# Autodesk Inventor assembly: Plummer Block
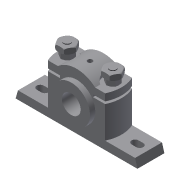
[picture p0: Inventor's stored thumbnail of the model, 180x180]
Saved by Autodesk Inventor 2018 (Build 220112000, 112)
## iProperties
Created: 2011-07
Part Number: Plummer Block
Document SubType Name: Assembly
Designer: CadCim
Author: CadCim
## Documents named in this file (7)
- E:\_Deepak\Inventor\Autodesk Inventor_2017_Project\Resources\Inventor_2018_tut\c09_Inv_tut_2018\c09_tut02_inv\Plummer Block\Plummer Block.iam
- E:\_Deepak\Inventor\Autodesk Inventor_2017_Project\Resources\Inventor_2018_tut\c09_Inv_tut_2018\c09_tut02_inv\Plummer Block\Casting.ipt
- E:\_Deepak\Inventor\Autodesk Inventor_2017_Project\Resources\Inventor_2018_tut\c09_Inv_tut_2018\c09_tut02_inv\Plummer Block\Brasses.ipt
- E:\_Deepak\Inventor\Autodesk Inventor_2017_Project\Resources\Inventor_2018_tut\c09_Inv_tut_2018\c09_tut02_inv\Plummer Block\Cap.ipt
- E:\_Deepak\Inventor\Autodesk Inventor_2017_Project\Resources\Inventor_2018_tut\c09_Inv_tut_2018\c09_tut02_inv\Plummer Block\Bolt.ipt
- E:\_Deepak\Inventor\Autodesk Inventor_2017_Project\Resources\Inventor_2018_tut\c09_Inv_tut_2018\c09_tut02_inv\Plummer Block\Nut.ipt
- E:\_Deepak\Inventor\Autodesk Inventor_2017_Project\Resources\Inventor_2018_tut\c09_Inv_tut_2018\c09_tut02_inv\Plummer Block\Lock Nut.ipt
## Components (9 placed, 6 different names)
1. Casting:1 — Mate:1, Mate:2, Insert:1, Angle:1, Insert:2, Angle:2
2. Brasses:1 — Mate:1, Mate:2, Mate:3, Mate:4
3. Cap:1 — Mate:3, Mate:4, Insert:4, Insert:5
4. Bolt:1 — Insert:1, Angle:1
5. Bolt:2 — Insert:2, Angle:2
6. Nut:2 — Insert:4, Insert:7
7. Nut:3 — Insert:5, Insert:6
8. Lock Nut:3 — Insert:6
9. Lock Nut:4 — Insert:7
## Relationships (12: Insert 6, Mate 4, Angle 2)
- Mate:1: Casting:1 ↔ Brasses:1
- Mate:2: Casting:1 ↔ Brasses:1
- Mate:3: Brasses:1 ↔ Cap:1
- Mate:4: Brasses:1 ↔ Cap:1
- Insert:1: Casting:1 ↔ Bolt:1
- Angle:1: Casting:1 ↔ Bolt:1
- Insert:2: Casting:1 ↔ Bolt:2
- Angle:2: Casting:1 ↔ Bolt:2
- Insert:4: Cap:1 ↔ Nut:2
- Insert:5: Cap:1 ↔ Nut:3
- Insert:6: Nut:3 ↔ Lock Nut:3
- Insert:7: Nut:2 ↔ Lock Nut:4
